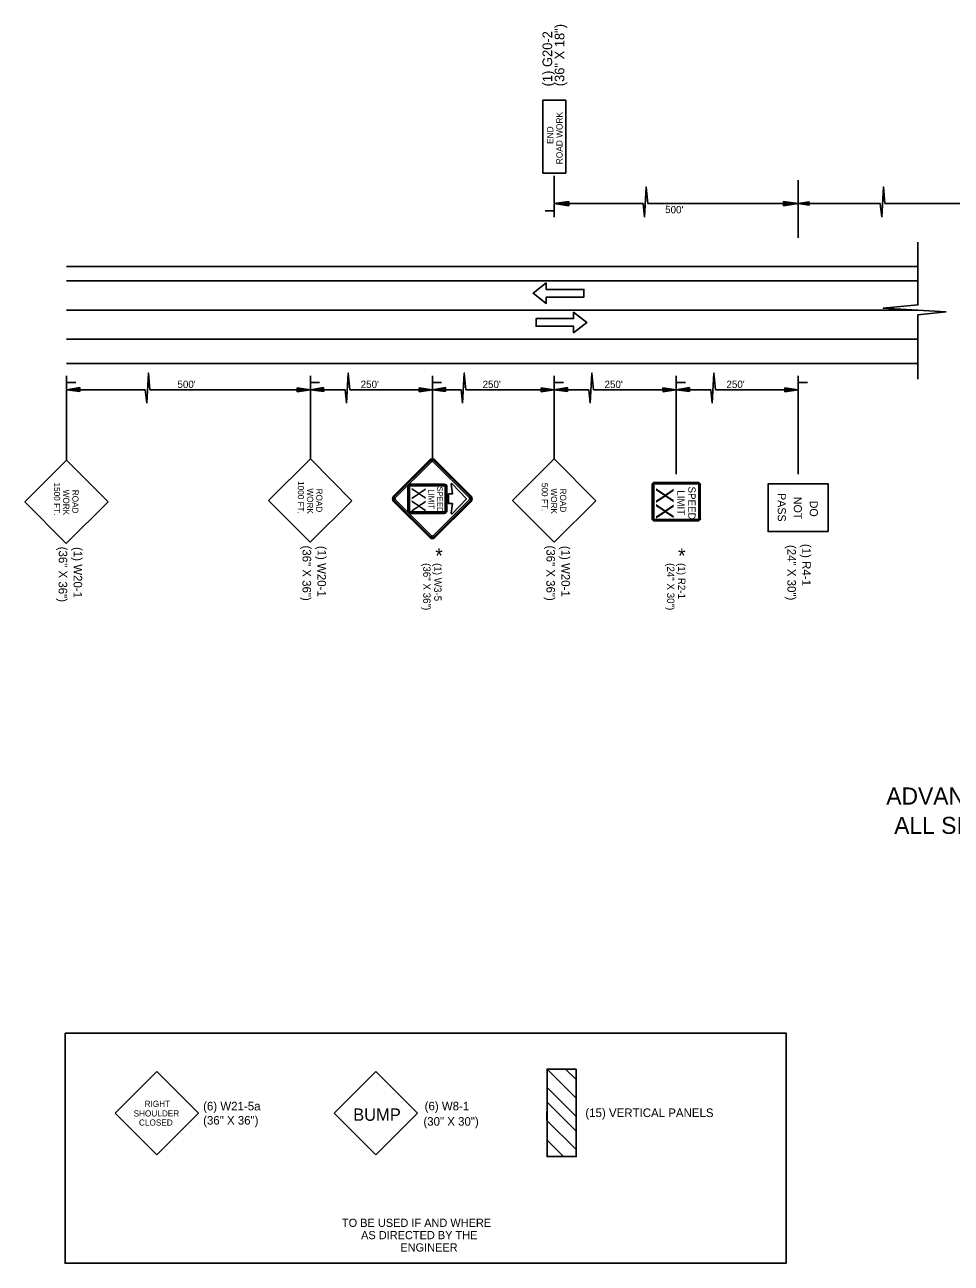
# Model space of a CAD drawing. Extents: x -160 to 6143532, y -375 to 762199.
# Drawn here: x -160.3 to -92.5, y 5.6 to 96.3 of the extents above; entities that cross this region are included whole.
import ezdxf

# ---------------------------------------------------------------- set-up
doc = ezdxf.new("R2010")
doc.units = 0
for name, color, linetype in [('B_Steel', 7, 'Continuous'), ('Level 1', 7, 'Continuous'), ('Level 3', 7, 'Continuous'), ('Level 42', 7, 'Continuous'), ('Level 8', 7, 'Continuous'), ('P_TC_Signs_Permanent', 7, 'Continuous'), ('R_Annotation', 7, 'Continuous'), ('R_Centerline', 7, 'Continuous'), ('R_Dimension', 7, 'Continuous'), ('R_Draft', 7, 'Continuous'), ('R_Striping', 7, 'Continuous')]:
    doc.layers.add(name, color=color, linetype=linetype)

msp = doc.modelspace()

# ---------------------------------------------------------------- linework, layer by layer
at = {"layer": 'Level 1'}
for p, q in [((-119.918, 19.832), (-122.053, 19.832)), ((-122.053, 19.832), (-120.699, 19.832)), ((-122.053, 19.832), (-119.918, 17.697)), ((-122.053, 19.832), (-119.927, 17.706)), ((-119.927, 17.706), (-122.053, 19.832)), ((-122.053, 13.427), (-122.053, 19.832)), ((-122.053, 19.832), (-122.053, 14.623)), ((-120.699, 19.832), (-119.921, 19.054)), ((-119.921, 19.054), (-120.699, 19.832)), ((-120.699, 19.832), (-119.918, 19.832)), ((-119.918, 19.832), (-119.921, 19.054)), ((-119.928, 16.357), (-122.054, 18.483)), ((-122.058, 16.064), (-122.053, 17.398)), ((-122.053, 17.398), (-119.927, 15.272)), ((-119.932, 13.938), (-122.058, 16.064)), ((-122.053, 14.623), (-120.857, 13.427)), ((-122.053, 13.427), (-122.053, 14.623)), ((-122.053, 14.623), (-120.857, 13.427)), ((-119.918, 13.427), (-122.053, 13.427)), ((-120.857, 13.427), (-122.053, 13.427))]:
    msp.add_line(p, q, dxfattribs=at)
at = {"layer": 'Level 3'}
for p, q in [((-121.537, 82.664), (-122.195, 82.664)), ((-121.523, 82.184), (-121.523, 83.148)), ((-157.227, 69.608), (-157.227, 70.572)), ((-157.213, 70.088), (-156.555, 70.088)), ((-139.375, 69.608), (-139.375, 70.572)), ((-139.361, 70.088), (-138.703, 70.088)), ((-130.449, 69.608), (-130.449, 70.572)), ((-130.435, 70.088), (-129.777, 70.088)), ((-121.522, 69.608), (-121.522, 70.572)), ((-121.508, 70.088), (-120.85, 70.088)), ((-112.596, 69.608), (-112.596, 70.572)), ((-112.582, 70.088), (-111.924, 70.088)), ((-103.67, 69.608), (-103.67, 70.572)), ((-103.656, 70.088), (-102.998, 70.088))]:
    msp.add_line(p, q, dxfattribs=at)
at = {"layer": 'Level 42'}
for p, q in [((-122.362, 90.763), (-122.362, 85.424)), ((-120.684, 90.763), (-122.362, 90.763)), ((-120.684, 90.763), (-120.684, 85.424)), ((-120.684, 85.424), (-122.362, 85.424))]:
    msp.add_line(p, q, dxfattribs=at)
msp.add_lwpolyline([(-119.918, 19.832), (-122.053, 19.832), (-122.053, 13.427), (-119.918, 13.427), (-119.918, 19.832)], dxfattribs=at)
at = {"layer": 'Level 8'}
for p, q in [((-160.285, 61.367), (-157.228, 64.409)), ((-154.186, 61.349), (-157.228, 64.409)), ((-142.433, 61.457), (-139.375, 64.498)), ((-136.333, 61.439), (-139.375, 64.498)), ((-124.58, 61.457), (-121.523, 64.498)), ((-118.481, 61.439), (-121.523, 64.498)), ((-157.245, 58.307), (-160.285, 61.367)), ((-157.245, 58.307), (-154.186, 61.349)), ((-139.393, 58.397), (-142.433, 61.457)), ((-139.393, 58.397), (-136.333, 61.439)), ((-121.541, 58.397), (-124.58, 61.457)), ((-121.541, 58.397), (-118.481, 61.439)), ((-150.626, 19.653), (-153.676, 16.602)), ((-147.575, 16.602), (-150.626, 19.653)), ((-137.635, 16.602), (-134.584, 19.653)), ((-134.584, 19.653), (-131.533, 16.602)), ((-150.625, 13.554), (-153.676, 16.602)), ((-147.575, 16.602), (-150.625, 13.554)), ((-137.635, 16.602), (-134.584, 13.551)), ((-134.584, 13.551), (-131.533, 16.602))]:
    msp.add_line(p, q, dxfattribs=at)
msp.add_lwpolyline([(-101.469, 59.171), (-105.871, 59.171), (-105.871, 62.664), (-101.469, 62.664)], close=True, dxfattribs=at)
at = {"layer": 'P_TC_Signs_Permanent'}
for p, q in [((-130.638, 64.42), (-133.289, 61.769)), ((-127.609, 61.769), (-130.26, 64.42)), ((-130.586, 64.367), (-133.237, 61.716)), ((-130.512, 64.294), (-133.163, 61.643)), ((-127.735, 61.643), (-130.386, 64.294)), ((-127.661, 61.716), (-130.312, 64.367)), ((-132.051, 62.651), (-129.576, 62.651)), ((-114.364, 62.603), (-114.364, 60.131)), ((-114.32, 62.603), (-114.32, 60.131)), ((-114.246, 62.603), (-114.246, 60.131)), ((-111.009, 62.779), (-114.187, 62.779)), ((-111.009, 62.735), (-114.187, 62.735)), ((-111.009, 62.662), (-114.187, 62.662)), ((-110.951, 60.131), (-110.951, 62.603)), ((-110.877, 60.131), (-110.877, 62.603)), ((-110.833, 60.131), (-110.833, 62.603)), ((-132.242, 60.699), (-132.242, 62.46)), ((-129.385, 62.46), (-129.385, 60.699)), ((-133.289, 61.39), (-130.638, 58.739)), ((-133.237, 61.443), (-130.586, 58.792)), ((-133.163, 61.517), (-130.512, 58.866)), ((-130.386, 58.866), (-127.735, 61.517)), ((-130.312, 58.792), (-127.661, 61.443)), ((-130.26, 58.739), (-127.609, 61.39)), ((-129.576, 60.509), (-132.051, 60.509)), ((-114.187, 60.072), (-111.009, 60.072)), ((-114.187, 59.999), (-111.009, 59.999)), ((-114.187, 59.955), (-111.009, 59.955))]:
    msp.add_line(p, q, dxfattribs=at)
for points in [[(-129.576, 62.603), (-132.051, 62.603)], [(-129.072, 62.648), (-128.983, 61.937), (-129.266, 61.937), (-129.266, 61.223), (-128.984, 61.223), (-129.072, 60.517)], [(-128.995, 60.481), (-127.957, 61.583), (-128.995, 62.684)], [(-132.194, 62.46), (-132.194, 60.699)], [(-132.123, 60.699), (-132.123, 62.46)], [(-132.051, 62.532), (-129.576, 62.532)], [(-129.504, 62.46), (-129.504, 61.58), (-129.504, 60.699)], [(-129.433, 60.699), (-129.433, 61.58), (-129.433, 62.46)], [(-129.576, 60.628), (-132.051, 60.628)], [(-132.051, 60.556), (-129.576, 60.556)]]:
    msp.add_lwpolyline(points, dxfattribs=at)
for centre, radius, start, end in [((-130.449, 64.231), 0.268, 45, 135), ((-130.449, 64.231), 0.193, 45, 135), ((-130.449, 64.231), 0.0893, 45, 135), ((-132.051, 62.46), 0.19, 90, 180), ((-132.051, 62.46), 0.143, 90, 180), ((-129.576, 62.46), 0.19, 0, 90), ((-129.576, 62.46), 0.143, 0, 90), ((-129.028, 62.653), 0.0446, 43.31166, 187.12501), ((-114.187, 62.603), 0.177, 90, 180), ((-114.187, 62.603), 0.132, 90, 180), ((-114.187, 62.603), 0.0588, 90, 180), ((-111.009, 62.603), 0.177, 360, 90), ((-111.009, 62.603), 0.132, 360, 90), ((-111.009, 62.603), 0.0588, 360, 90), ((-133.1, 61.58), 0.268, 135, 225), ((-133.1, 61.58), 0.193, 135, 225), ((-132.051, 62.46), 0.0714, 90, 180), ((-129.576, 62.46), 0.0714, 0, 90), ((-127.798, 61.58), 0.193, 315, 45), ((-127.798, 61.58), 0.268, 315, 45), ((-133.1, 61.58), 0.0893, 135, 225), ((-127.798, 61.58), 0.0893, 315, 45), ((-132.051, 60.699), 0.19, 180, 270), ((-132.051, 60.699), 0.143, 180, 270), ((-132.051, 60.699), 0.0714, 180, 270), ((-129.576, 60.699), 0.19, 270, 0), ((-129.576, 60.699), 0.143, 270, 0), ((-129.576, 60.699), 0.0714, 270, 0), ((-129.028, 60.512), 0.0446, 172.87498, 316.68834), ((-114.187, 60.131), 0.177, 180, 270), ((-114.187, 60.131), 0.132, 180, 270), ((-114.187, 60.131), 0.0588, 180, 270), ((-111.009, 60.131), 0.177, 270, 360), ((-111.009, 60.131), 0.132, 270, 360), ((-111.009, 60.131), 0.0588, 270, 360), ((-130.449, 58.929), 0.268, 225, 315), ((-130.449, 58.929), 0.193, 225, 315), ((-130.449, 58.929), 0.0893, 225, 315)]:
    msp.add_arc(centre, radius, start, end, dxfattribs=at)
at = {"layer": 'R_Annotation'}
msp.add_lwpolyline([(-157.334, 22.459), (-104.558, 22.459), (-104.558, 5.614), (-157.334, 5.614)], close=True, dxfattribs=at)
at = {"layer": 'R_Centerline'}
msp.add_line((-157.228, 75.39), (-94.913, 75.39), dxfattribs=at)
at = {"layer": 'R_Dimension'}
for p, q in [((-121.523, 83.188), (-121.523, 85.228)), ((-103.67, 80.671), (-103.67, 84.903)), ((-120.454, 83.349), (-121.523, 83.188)), ((-121.523, 83.188), (-115.028, 83.188)), ((-120.454, 83.028), (-121.523, 83.188)), ((-120.454, 83.322), (-121.344, 83.188)), ((-120.454, 83.055), (-121.344, 83.188)), ((-120.454, 83.295), (-121.161, 83.188)), ((-120.454, 83.082), (-121.161, 83.188)), ((-120.454, 83.268), (-120.982, 83.188)), ((-120.454, 83.109), (-120.982, 83.188)), ((-120.454, 83.24), (-120.802, 83.188)), ((-120.454, 83.136), (-120.802, 83.188)), ((-120.454, 83.213), (-120.623, 83.188)), ((-120.454, 83.163), (-120.623, 83.188)), ((-120.454, 83.028), (-120.454, 83.349)), ((-114.681, 83.188), (-103.67, 83.188)), ((-104.739, 83.349), (-103.67, 83.188)), ((-104.739, 83.349), (-104.739, 83.028)), ((-104.739, 83.322), (-103.849, 83.188)), ((-104.739, 83.295), (-104.033, 83.188)), ((-104.739, 83.268), (-104.21, 83.188)), ((-104.739, 83.24), (-104.392, 83.188)), ((-104.739, 83.213), (-104.57, 83.188)), ((-104.739, 83.028), (-103.67, 83.188)), ((-104.739, 83.136), (-104.392, 83.188)), ((-104.739, 83.082), (-104.033, 83.188)), ((-104.739, 83.055), (-103.849, 83.188)), ((-104.739, 83.109), (-104.21, 83.188)), ((-104.739, 83.163), (-104.57, 83.188)), ((-97.665, 83.188), (-103.67, 83.188)), ((-102.86, 83.31), (-103.669, 83.188)), ((-102.86, 83.067), (-103.669, 83.188)), ((-102.86, 83.289), (-103.534, 83.188)), ((-102.86, 83.087), (-103.534, 83.188)), ((-102.86, 83.269), (-103.395, 83.188)), ((-102.86, 83.108), (-103.395, 83.188)), ((-102.86, 83.249), (-103.26, 83.188)), ((-102.86, 83.128), (-103.26, 83.188)), ((-102.86, 83.228), (-103.123, 83.188)), ((-102.86, 83.149), (-103.123, 83.188)), ((-102.86, 83.207), (-102.988, 83.188)), ((-102.86, 83.169), (-102.988, 83.188)), ((-102.86, 83.067), (-102.86, 83.31)), ((-76.166, 83.188), (-97.318, 83.188)), ((-156.259, 69.725), (-157.228, 69.563)), ((-157.228, 69.563), (-157.228, 64.409)), ((-156.254, 69.433), (-157.228, 69.563)), ((-151.468, 69.563), (-157.228, 69.563)), ((-156.258, 69.7), (-157.065, 69.566)), ((-156.255, 69.457), (-157.065, 69.566)), ((-156.258, 69.675), (-156.899, 69.569)), ((-156.255, 69.482), (-156.899, 69.569)), ((-156.257, 69.651), (-156.737, 69.571)), ((-156.255, 69.507), (-156.737, 69.571)), ((-156.257, 69.626), (-156.572, 69.574)), ((-156.256, 69.532), (-156.572, 69.574)), ((-156.257, 69.602), (-156.41, 69.577)), ((-156.256, 69.556), (-156.41, 69.577)), ((-156.254, 69.433), (-156.259, 69.725)), ((-139.375, 69.563), (-151.121, 69.563)), ((-140.348, 69.693), (-139.375, 69.563)), ((-140.348, 69.693), (-140.344, 69.402)), ((-140.348, 69.669), (-139.537, 69.56)), ((-140.348, 69.644), (-139.704, 69.558)), ((-140.347, 69.62), (-139.866, 69.555)), ((-140.347, 69.595), (-140.031, 69.553)), ((-140.346, 69.571), (-140.193, 69.55)), ((-140.346, 69.5), (-140.031, 69.553)), ((-140.346, 69.525), (-140.193, 69.55)), ((-140.345, 69.451), (-139.704, 69.558)), ((-140.345, 69.475), (-139.866, 69.555)), ((-140.344, 69.402), (-139.375, 69.563)), ((-140.344, 69.426), (-139.537, 69.56)), ((-138.406, 69.725), (-139.375, 69.563)), ((-138.402, 69.433), (-139.375, 69.563)), ((-139.375, 69.563), (-139.375, 64.498)), ((-136.832, 69.563), (-139.375, 69.563)), ((-138.406, 69.7), (-139.213, 69.566)), ((-138.402, 69.457), (-139.213, 69.566)), ((-138.406, 69.675), (-139.046, 69.569)), ((-138.403, 69.482), (-139.046, 69.569)), ((-138.405, 69.651), (-138.884, 69.571)), ((-138.403, 69.507), (-138.884, 69.571)), ((-138.405, 69.626), (-138.72, 69.574)), ((-138.403, 69.532), (-138.72, 69.574)), ((-138.404, 69.602), (-138.557, 69.577)), ((-138.403, 69.556), (-138.557, 69.577)), ((-138.402, 69.433), (-138.406, 69.725)), ((-130.449, 69.563), (-136.485, 69.563)), ((-131.422, 69.693), (-130.449, 69.563)), ((-131.422, 69.693), (-131.418, 69.402)), ((-131.422, 69.669), (-130.611, 69.56)), ((-131.421, 69.644), (-130.778, 69.558)), ((-131.421, 69.62), (-130.94, 69.555)), ((-131.421, 69.595), (-131.105, 69.553)), ((-131.42, 69.571), (-131.266, 69.55)), ((-131.42, 69.525), (-131.266, 69.55)), ((-131.419, 69.451), (-130.778, 69.558)), ((-131.419, 69.475), (-130.94, 69.555)), ((-131.419, 69.5), (-131.105, 69.553)), ((-131.418, 69.402), (-130.449, 69.563)), ((-131.418, 69.426), (-130.611, 69.56)), ((-129.48, 69.725), (-130.449, 69.563)), ((-129.476, 69.433), (-130.449, 69.563)), ((-130.449, 69.563), (-130.449, 64.498)), ((-128.34, 69.563), (-130.449, 69.563)), ((-129.48, 69.7), (-130.287, 69.566)), ((-129.476, 69.457), (-130.287, 69.566)), ((-129.479, 69.675), (-130.12, 69.569)), ((-129.476, 69.482), (-130.12, 69.569)), ((-129.479, 69.651), (-129.958, 69.571)), ((-129.477, 69.507), (-129.958, 69.571)), ((-129.478, 69.626), (-129.793, 69.574)), ((-129.477, 69.532), (-129.793, 69.574)), ((-129.478, 69.602), (-129.631, 69.577)), ((-129.477, 69.556), (-129.631, 69.577)), ((-129.476, 69.433), (-129.48, 69.725)), ((-121.523, 69.563), (-127.993, 69.563)), ((-122.496, 69.693), (-121.523, 69.563)), ((-122.496, 69.693), (-122.492, 69.402)), ((-122.496, 69.669), (-121.685, 69.56)), ((-122.495, 69.644), (-121.852, 69.558)), ((-122.495, 69.62), (-122.014, 69.555)), ((-122.494, 69.595), (-122.178, 69.553)), ((-122.494, 69.571), (-122.34, 69.55)), ((-122.494, 69.525), (-122.34, 69.55)), ((-122.493, 69.475), (-122.014, 69.555)), ((-122.493, 69.5), (-122.178, 69.553)), ((-122.492, 69.402), (-121.523, 69.563)), ((-122.492, 69.426), (-121.685, 69.56)), ((-122.492, 69.451), (-121.852, 69.558)), ((-120.554, 69.725), (-121.523, 69.563)), ((-121.523, 69.563), (-121.523, 64.498)), ((-120.549, 69.433), (-121.523, 69.563)), ((-118.994, 69.563), (-121.523, 69.563)), ((-120.554, 69.7), (-121.36, 69.566)), ((-120.55, 69.457), (-121.36, 69.566)), ((-120.553, 69.675), (-121.194, 69.569)), ((-120.55, 69.482), (-121.194, 69.569)), ((-120.553, 69.651), (-121.032, 69.571)), ((-120.551, 69.507), (-121.032, 69.571)), ((-120.552, 69.626), (-120.867, 69.574)), ((-120.551, 69.532), (-120.867, 69.574)), ((-120.552, 69.602), (-120.705, 69.577)), ((-120.551, 69.556), (-120.705, 69.577)), ((-120.549, 69.433), (-120.554, 69.725)), ((-112.597, 69.563), (-118.647, 69.563)), ((-113.57, 69.693), (-112.597, 69.563)), ((-113.57, 69.693), (-113.565, 69.402)), ((-113.569, 69.669), (-112.759, 69.56)), ((-113.569, 69.644), (-112.926, 69.558)), ((-113.569, 69.62), (-113.087, 69.555)), ((-113.568, 69.595), (-113.252, 69.553)), ((-113.568, 69.571), (-113.414, 69.55)), ((-113.567, 69.475), (-113.087, 69.555)), ((-113.567, 69.5), (-113.252, 69.553)), ((-113.567, 69.525), (-113.414, 69.55)), ((-113.566, 69.426), (-112.759, 69.56)), ((-113.566, 69.451), (-112.926, 69.558)), ((-113.565, 69.402), (-112.597, 69.563)), ((-111.628, 69.725), (-112.597, 69.563)), ((-112.597, 69.563), (-112.597, 63.381)), ((-110.068, 69.563), (-112.597, 69.563)), ((-111.623, 69.433), (-112.597, 69.563)), ((-111.627, 69.7), (-112.434, 69.566)), ((-111.624, 69.457), (-112.434, 69.566)), ((-111.627, 69.675), (-112.268, 69.569)), ((-111.624, 69.482), (-112.268, 69.569)), ((-111.627, 69.651), (-112.106, 69.571)), ((-111.624, 69.507), (-112.106, 69.571)), ((-111.626, 69.626), (-111.941, 69.574)), ((-111.625, 69.532), (-111.941, 69.574)), ((-111.626, 69.602), (-111.779, 69.577)), ((-111.625, 69.556), (-111.779, 69.577)), ((-111.623, 69.433), (-111.628, 69.725)), ((-103.67, 69.563), (-109.721, 69.563)), ((-104.644, 69.693), (-103.67, 69.563)), ((-104.644, 69.693), (-104.639, 69.402)), ((-104.643, 69.669), (-103.833, 69.56)), ((-104.643, 69.644), (-103.999, 69.558)), ((-104.642, 69.62), (-104.161, 69.555)), ((-104.642, 69.595), (-104.326, 69.553)), ((-104.642, 69.571), (-104.488, 69.55)), ((-104.641, 69.5), (-104.326, 69.553)), ((-104.641, 69.525), (-104.488, 69.55)), ((-104.64, 69.426), (-103.833, 69.56)), ((-104.64, 69.451), (-103.999, 69.558)), ((-104.64, 69.475), (-104.161, 69.555)), ((-104.639, 69.402), (-103.67, 69.563)), ((-103.67, 69.563), (-103.67, 63.381))]:
    msp.add_line(p, q, dxfattribs=at)
for points in [[(-114.681, 83.188), (-114.799, 84.407), (-114.92, 82.195)], [(-97.318, 83.188), (-97.435, 84.407), (-97.557, 82.195)], [(-114.92, 82.195), (-115.028, 83.188)], [(-97.557, 82.195), (-97.665, 83.188)], [(-94.908, 80.363), (-94.908, 75.773), (-97.439, 75.529), (-92.846, 75.277)], [(-92.846, 75.277), (-94.908, 75.052), (-94.908, 70.334)], [(-151.121, 69.563), (-151.238, 70.782), (-151.36, 68.57)], [(-136.485, 69.563), (-136.602, 70.782), (-136.724, 68.57)], [(-127.993, 69.563), (-128.111, 70.782), (-128.232, 68.57)], [(-118.647, 69.563), (-118.764, 70.782), (-118.886, 68.57)], [(-109.721, 69.563), (-109.838, 70.782), (-109.96, 68.57)], [(-151.36, 68.57), (-151.468, 69.563)], [(-136.724, 68.57), (-136.832, 69.563)], [(-128.232, 68.57), (-128.34, 69.563)], [(-118.886, 68.57), (-118.994, 69.563)], [(-109.96, 68.57), (-110.068, 69.563)]]:
    msp.add_lwpolyline(points, dxfattribs=at)
at = {"layer": 'R_Draft'}
for p, q in [((-157.228, 78.595), (-104.752, 78.595)), ((-104.752, 78.595), (-94.913, 78.595)), ((-157.228, 77.527), (-104.752, 77.527)), ((-104.752, 77.527), (-94.913, 77.527)), ((-157.228, 73.253), (-104.752, 73.253)), ((-104.752, 73.253), (-94.913, 73.253)), ((-157.228, 71.473), (-104.752, 71.473)), ((-104.752, 71.473), (-94.913, 71.473))]:
    msp.add_line(p, q, dxfattribs=at)
at = {"layer": 'R_Striping'}
for points in [[(-122.108, 77.377), (-123.08, 76.629), (-122.108, 75.88), (-122.108, 76.348), (-119.355, 76.348), (-119.355, 76.909), (-122.108, 76.909)], [(-120.107, 73.737), (-119.135, 74.486), (-120.107, 75.234), (-120.107, 74.766), (-122.86, 74.766), (-122.86, 74.205), (-120.107, 74.205)]]:
    msp.add_lwpolyline(points, close=True, dxfattribs=at)

# ---------------------------------------------------------------- texts
at = {"layer": 'B_Steel'}
msp.add_text('BUMP', height=0.9034, dxfattribs=at).set_placement((-136.247, 16.042))
at = {"layer": 'Level 42'}
for s, p in [('ROAD WORK', (-120.921, 86.07)), ('END', (-121.594, 87.558))]:
    msp.add_text(s, height=0.4558, rotation=90.00145, dxfattribs=at).set_placement(p)
at = {"layer": 'Level 8'}
for s, height, rotation, p in [('(36" X 18")', 0.70664, 90.00145, (-120.785, 91.781)), ('(1) G20-2', 0.7066, 90.00145, (-121.677, 91.769)), ('1500 FT.', 0.4495, 269.83127, (-158.146, 62.769)), ('1000 FT.', 0.4495, 269.83127, (-140.294, 62.877)), ('500 FT. ', 0.4495, 269.83127, (-122.441, 62.745)), ('WORK', 0.4494, 269.83074, (-157.474, 62.249)), ('ROAD', 0.4495, 269.83115, (-156.799, 62.238)), ('WORK', 0.4494, 269.83074, (-139.621, 62.339)), ('ROAD', 0.4495, 269.83115, (-138.947, 62.328)), ('XX', 1.0233, 270, (-131.965, 62.419)), ('LIMIT', 0.4224, 270, (-130.734, 62.263)), ('SPEED ', 0.4224, 270, (-130.1, 62.48)), ('WORK', 0.4494, 269.83074, (-121.769, 62.339)), ('ROAD', 0.4495, 269.83115, (-121.095, 62.328)), ('XX', 1.2976, 270, (-114.077, 62.4)), ('LIMIT', 0.5357, 270, (-112.517, 62.202)), ('SPEED ', 0.5357, 270, (-111.713, 62.476)), ('PASS', 0.5859, 270, (-105.162, 61.998)), ('NOT', 0.5859, 270, (-103.99, 61.725)), ('DO', 0.5859, 270, (-102.818, 61.439)), ('(36" X 36")', 0.62813, 269.8307, (-139.947, 58.161)), ('(1) W20-1', 0.6281, 269.8307, (-138.854, 58.135)), ('(36" X 36")', 0.62813, 269.8307, (-122.095, 58.161)), ('(1) W20-1', 0.6281, 269.8307, (-121.002, 58.135)), ('(24" X 30")', 0.62813, 270, (-104.463, 58.195)), ('(1) R4-1', 0.6281, 270, (-103.375, 58.274)), ('(36" X 36")', 0.62813, 269.8307, (-157.8, 58.071)), ('(1) W20-1', 0.6281, 269.8307, (-156.707, 58.045)), ('RIGHT', 0.4495, 0.00057, (-151.516, 17.059)), ('SHOULDER', 0.4495, 0.00045, (-152.321, 16.357)), ('CLOSED', 0.4495, 0.00057, (-151.925, 15.688))]:
    msp.add_text(s, height=height, rotation=rotation, dxfattribs=at).set_placement(p)
for s, height, p in [('(6) W21-5a', 0.6281, (-147.229, 16.802)), ('(6) W8-1', 0.6281, (-131.013, 16.805)), ('(36" X 36")', 0.62813, (-147.229, 15.762)), ('(30" X 30")', 0.62813, (-131.105, 15.683)), ('(15) VERTICAL PANELS', 0.62813, (-119.248, 16.315))]:
    msp.add_text(s, height=height, dxfattribs=at).set_placement(p)
at = {"layer": 'R_Annotation'}
for s, height, rotation, p in [("500'", 0.5356, 358.76961, (-113.412, 82.494)), ("500'", 0.5356, 360, (-149.107, 69.69)), ("250'", 0.5356, 360, (-135.696, 69.69)), ("250'", 0.5356, 360, (-126.77, 69.69)), ("250'", 0.5356, 360, (-117.844, 69.69)), ("250'", 0.5356, 360, (-108.918, 69.69)), ('(36" X 36")', 0.53557, 270, (-131.118, 56.869)), ('(1) W3-5', 0.5356, 270, (-130.315, 56.869)), ('(24" X 30")', 0.53557, 270, (-113.266, 56.869)), ('(1) R2-1', 0.5356, 270, (-112.463, 56.869))]:
    msp.add_text(s, height=height, rotation=rotation, dxfattribs=at).set_placement(p)
for s, height, p in [('*', 1.071, (-130.239, 56.879)), ('*', 1.071, (-112.466, 56.879)), ('ADVANCE WARNING DETAILS ', 1.25, (-97.22, 39.193)), ('ALL SITES - ALL STAGES', 1.25, (-96.64, 37.043)), ('TO BE USED IF AND WHERE ', 0.6, (-137.067, 8.272)), ('AS DIRECTED BY THE ', 0.6, (-135.664, 7.372)), ('ENGINEER', 0.6, (-132.794, 6.472))]:
    msp.add_text(s, height=height, dxfattribs=at).set_placement(p)

doc.saveas('drawing.dxf')
